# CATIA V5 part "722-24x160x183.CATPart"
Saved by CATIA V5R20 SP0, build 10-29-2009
Part number: 722-24x160x183
Definition: NONE
Nomenclature: 722-24x160x183
Source: Unknown
Description: 722-24x160x183
Bounding box of the stored display mesh (mm): x -12 to 12, y -12 to 12, z -148 to 35
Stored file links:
  C:\Users\Utente\Desktop\IO LAVORO\3D X SITO CF\X SITO\722\722-24x160x183.CATPart
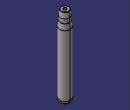
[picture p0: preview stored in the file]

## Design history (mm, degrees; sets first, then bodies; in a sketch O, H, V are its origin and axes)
Body1 "722-24x160x183" (main body)
  Solid1: solid without history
